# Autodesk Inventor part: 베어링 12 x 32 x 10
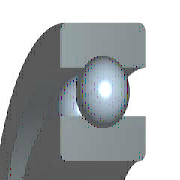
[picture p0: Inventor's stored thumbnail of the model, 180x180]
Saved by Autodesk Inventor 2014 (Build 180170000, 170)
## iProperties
IsCustomPart: 1
Created: 2012-02
Part Number: 베어링 12 x 32 x 10
Material: 강철, 연강
Description: 깊은 그루브 볼 베어링
Document SubType Name: Modeling
Standard: KS B 2023
Designer: test
Standards Organization: KS
Language: ko-KR
Size Designation: 6201 - 12 x 32 x 10
Categories: <MemberInstance><Categories><Category DisplayName="샤프트 부품" InternalName="7f7aeb1f-a693-4053-b835-cee3144e0d98" Mnemonic="SHFT"><Category DisplayName="베어링" Inter
Density: 1 g/cm^3
Appearance: Steel
Author: test
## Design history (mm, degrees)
sketch "스케치" dims "d0" = 5.2 (= -0.26 x WD + 0.26 x BD)
  geometry: L1 (2.4, 11)-(7.6, 11); L2 (5, 11)-(5, 8.4); L3 (5, 11)-(5, 13.6); L4 (3.068, 9.26)-(0, 9.26); L5 (0, 6)-(10, 6); L6 (3.068, 12.74)-(0, 12.74); L7 (0, 16)-(10, 16); L8 (10, 6)-(10, 9.26); L9 (6.932, 9.26)-(10, 9.26); L10 (6.932, 12.74)-(10, 12.74); L11 (10, 16)-(10, 12.74); L12 (-1.4, 0)-(8.4, 0) reference; L13 (0, -0.3)-(0, 5.3) reference
  constraints: 22 end point, 4 point on line, 2 collinear, 2 perpendicular, 2 symmetric about line, 1 midpoint, 1 parallel, 14 other
  dimensions: "d9" = 12 diameter of L5 L12 (= WD); "d11" = 32 diameter of L7 L12 (= BD); "d12" = 10 distance between parallel lines of L8 L13 (= KB); "d13" = 18.52 diameter of L9 L12 (= 0.326 x BD + 0.674 x WD)
revolve "본체" stored, may be unused: angle "d6" = 90 deg
revolve "볼" stored, may be unused: angle "d7" = 90 deg
pattern_circular "IDS_ARRAYBALL[SIMPL:T]" dims angle "d3" = 360 deg
body "Solid1"
fillet "모깎기1" dims "d1" = 0.6 (= KRS)
other parameters: "WD" = 12 [user parameter; used in 5 equation terms], "BD" = 32 [user parameter; used in 5 equation terms], "KB" = 10 [user parameter; used in 1 equation term], "KRS" = 0.6 [user parameter; used in 1 equation term], "d4" = 0, "d5" = 0, "d8" = 0, "d14" = 0, "d15" = 0, "BBA" = 0 [user parameter], "BC0" = 3100000 [user parameter], "BC" = 6890000 [user parameter], "BR" = 16 (= 0.5 x BD) [user parameter], "WR" = 6 (= 0.5 x WD) [user parameter]
